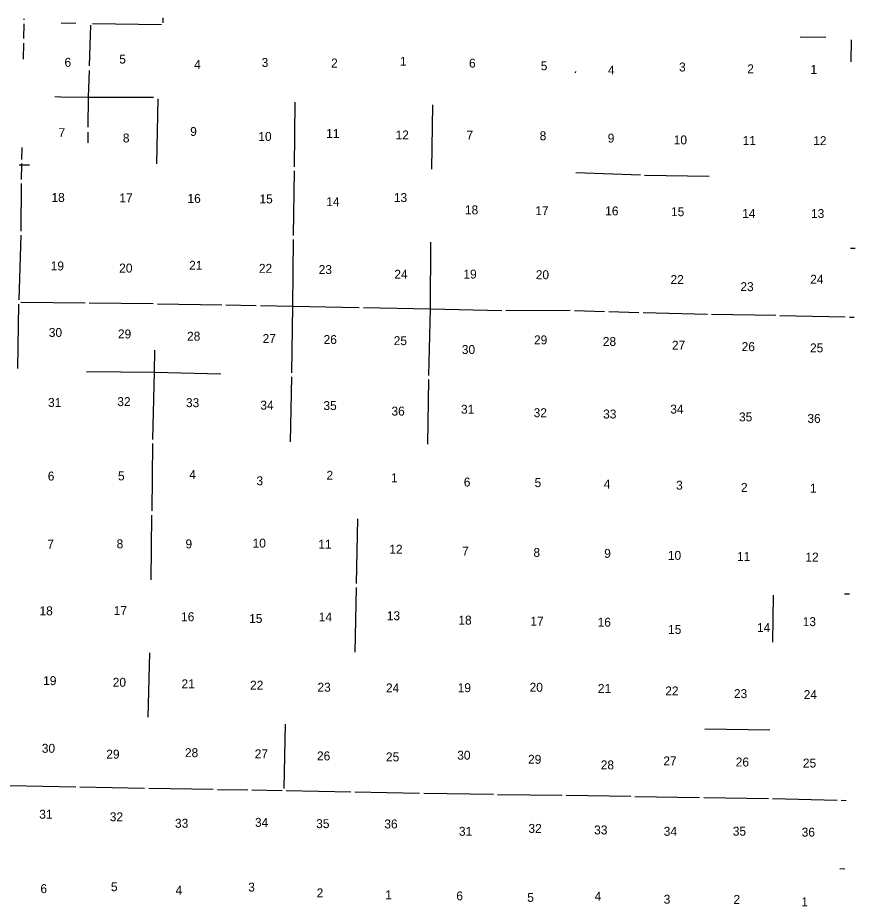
# Model space of a CAD drawing. Extents: x -2933025 to 31692252, y -2344676 to 23854604.
# Drawn here: x -2866805 to -2802466, y -2283621 to -2215327 of the extents above; entities that cross this region are included whole.
import ezdxf

# ---------------------------------------------------------------- set-up
doc = ezdxf.new("R2010")
doc.units = 0
doc.layers.add('tdCoSectLinePart', color=7, linetype='Continuous')
doc.layers.add('tdCoSectNmbr', color=7, linetype='Continuous')

msp = doc.modelspace()

# ---------------------------------------------------------------- linework, layer by layer
at = {"layer": 'tdCoSectLinePart'}
for points in [[(-2866313, -2215488), (-2866311, -2215399)], [(-2855629, -2215718), (-2855642, -2215327)], [(-2866337, -2216910), (-2866318, -2215805)], [(-2863484, -2215711), (-2862333, -2215737)], [(-2861293, -2219033), (-2861189, -2215891)], [(-2861061, -2215765), (-2855771, -2215853)], [(-2806705, -2216789), (-2804719, -2216827)], [(-2866366, -2218516), (-2866344, -2217282)], [(-2802771, -2218724), (-2802743, -2217021)], [(-2861373, -2221424), (-2861305, -2219382)], [(-2823945, -2219549), (-2823941, -2219450)], [(-2863951, -2221387), (-2863497, -2221393)], [(-2863494, -2221393), (-2861373, -2221424)], [(-2861395, -2223734), (-2861373, -2221424)], [(-2861373, -2221424), (-2856373, -2221442)], [(-2856109, -2226557), (-2856026, -2221560)], [(-2845544, -2226782), (-2845485, -2221821)], [(-2834998, -2226973), (-2834919, -2222014)], [(-2861407, -2224952), (-2861399, -2224111)], [(-2866492, -2226209), (-2866478, -2225298)], [(-2866709, -2226627), (-2866499, -2226632)], [(-2866510, -2227757), (-2866499, -2226632)], [(-2866499, -2226632), (-2866497, -2226536)], [(-2866499, -2226632), (-2865902, -2226638)], [(-2845620, -2232051), (-2845549, -2227099)], [(-2823939, -2227230), (-2818963, -2227413)], [(-2818646, -2227422), (-2813692, -2227513)], [(-2866549, -2231720), (-2866513, -2228074)], [(-2866711, -2237018), (-2866555, -2232037)], [(-2845676, -2237501), (-2845624, -2232367)], [(-2835102, -2237711), (-2835071, -2232575)], [(-2802839, -2233036), (-2802466, -2233044)], [(-2866558, -2237179), (-2861631, -2237235)], [(-2861315, -2237239), (-2856398, -2237301)], [(-2866802, -2242295), (-2866719, -2237334)], [(-2856081, -2237306), (-2851124, -2237389)], [(-2850808, -2237395), (-2848485, -2237443)], [(-2848168, -2237450), (-2845676, -2237501)], [(-2845753, -2242619), (-2845676, -2237501)], [(-2845676, -2237501), (-2840577, -2237604)], [(-2840255, -2237610), (-2835102, -2237711)], [(-2835224, -2242820), (-2835102, -2237711)], [(-2835102, -2237711), (-2829616, -2237817)], [(-2829299, -2237820), (-2824357, -2237813)], [(-2824041, -2237818), (-2821724, -2237896)], [(-2821407, -2237907), (-2819085, -2237985)], [(-2818768, -2237994), (-2813818, -2238113)], [(-2813502, -2238120), (-2808571, -2238197)], [(-2808255, -2238203), (-2803235, -2238325)], [(-2802918, -2238334), (-2802549, -2238345)], [(-2856307, -2242570), (-2856284, -2240878)], [(-2861513, -2242515), (-2856307, -2242570)], [(-2856419, -2247733), (-2856307, -2242570)], [(-2856307, -2242570), (-2851205, -2242686)], [(-2845864, -2247921), (-2845759, -2242936)], [(-2835302, -2248113), (-2835230, -2243139)], [(-2856491, -2253237), (-2856425, -2248050)], [(-2856566, -2258522), (-2856495, -2253553)], [(-2840770, -2258810), (-2840673, -2253843)], [(-2840880, -2264093), (-2840776, -2259127)], [(-2808788, -2263324), (-2808735, -2259707)], [(-2803278, -2259595), (-2802903, -2259616)], [(-2856776, -2269088), (-2856665, -2264136)], [(-2846342, -2274573), (-2846243, -2269619)], [(-2814014, -2269988), (-2809021, -2270070)], [(-2867418, -2274344), (-2862357, -2274442)], [(-2862040, -2274448), (-2857061, -2274535)], [(-2856744, -2274541), (-2851781, -2274633)], [(-2851465, -2274639), (-2849142, -2274681)], [(-2848825, -2274686), (-2846504, -2274728)], [(-2846187, -2274734), (-2841222, -2274823)], [(-2840905, -2274828), (-2835936, -2274918)], [(-2835621, -2274924), (-2830264, -2275016)], [(-2829947, -2275021), (-2824981, -2275091)], [(-2824664, -2275096), (-2819704, -2275172)], [(-2819387, -2275177), (-2814423, -2275255)], [(-2814106, -2275260), (-2809138, -2275343)], [(-2808821, -2275350), (-2803853, -2275468)], [(-2803536, -2275478), (-2803167, -2275494)], [(-2803644, -2280724), (-2803275, -2280745)]]:
    msp.add_lwpolyline(points, dxfattribs=at)

# ---------------------------------------------------------------- texts
at = {"layer": 'tdCoSectNmbr'}
for s, height, rotation, p in [('5', 686, 359.93563, (-2859007, -2218848)), ('6', 686, 359.93488, (-2863215, -2219093)), ('4', 686, 359.93644, (-2853263, -2219269)), ('3', 686, 359.93719, (-2848068, -2219103)), ('2', 686, 359.93796, (-2842735, -2219151)), ('1', 686, 359.93871, (-2837451, -2219017)), ('6', 686, 359.93949, (-2832136, -2219156)), ('5', 686, 359.94029, (-2826625, -2219372)), ('3', 686, 359.9424, (-2816000, -2219455)), ('4', 686, 359.94161, (-2821461, -2219684)), ('2', 686, 359.94316, (-2810762, -2219595)), ('1', 686, 359.94385, (-2805906, -2219641)), ('7', 686, 359.93499, (-2863675, -2224500)), ('8', 686, 359.9357, (-2858732, -2224912)), ('9', 686, 359.93644, (-2853560, -2224412)), ('10', 686.4, 359.93723, (-2848323, -2224791)), ('11', 686.4, 359.93797, (-2843114, -2224567)), ('12', 686.4, 359.93875, (-2837780, -2224680)), ('7', 686, 359.93951, (-2832332, -2224695)), ('8', 686, 359.94033, (-2826710, -2224743)), ('9', 686, 359.94162, (-2821483, -2224922)), ('10', 686.4, 359.94238, (-2816409, -2225057)), ('11', 686.4, 359.94314, (-2811114, -2225100)), ('12', 686.4, 359.94393, (-2805697, -2225117)), ('18', 686.4, 359.93497, (-2864217, -2229483)), ('17', 686.4, 359.93573, (-2859003, -2229520)), ('16', 686.4, 359.93648, (-2853767, -2229553)), ('15', 686.4, 359.93728, (-2848237, -2229596)), ('13', 686.4, 359.93877, (-2837911, -2229494)), ('14', 686.4, 359.93802, (-2843106, -2229808)), ('18', 686.4, 359.93957, (-2832452, -2230439)), ('17', 686.4, 359.94035, (-2827044, -2230499)), ('16', 686.4, 359.94163, (-2821678, -2230517)), ('15', 686.4, 359.94236, (-2816617, -2230576)), ('14', 686.4, 359.94316, (-2811151, -2230719)), ('13', 686.4, 359.94392, (-2805864, -2230721)), ('19', 686.4, 359.93502, (-2864274, -2234747)), ('20', 686.4, 359.93576, (-2859015, -2234911)), ('21', 686.4, 359.93653, (-2853641, -2234699)), ('22', 686.4, 359.9373, (-2848284, -2234932)), ('23', 686.4, 359.93799, (-2843686, -2235026)), ('24', 686.4, 359.93883, (-2837875, -2235387)), ('19', 686.4, 359.93959, (-2832567, -2235375)), ('20', 686.4, 359.9404, (-2827010, -2235420)), ('22', 686.4, 359.94238, (-2816657, -2235789)), ('24', 686.4, 359.94393, (-2805926, -2235770)), ('23', 686.4, 359.94315, (-2811288, -2236339)), ('30', 686.4, 359.93504, (-2864422, -2239858)), ('29', 686.4, 359.93581, (-2859111, -2239975)), ('28', 686.4, 359.93658, (-2853803, -2240146)), ('27', 686.4, 359.93741, (-2847996, -2240330)), ('26', 686.4, 359.93809, (-2843309, -2240404)), ('25', 686.4, 359.93887, (-2837925, -2240492)), ('29', 686.4, 359.94042, (-2827144, -2240431)), ('28', 686.4, 359.94164, (-2821858, -2240554)), ('30', 686.4, 359.93963, (-2832690, -2241171)), ('27', 686.4, 359.94241, (-2816548, -2240841)), ('26', 686.4, 359.94318, (-2811193, -2240952)), ('25', 686.4, 359.94394, (-2805940, -2241043)), ('31', 686.4, 359.93505, (-2864480, -2245239)), ('32', 686.4, 359.93585, (-2859161, -2245176)), ('33', 686.4, 359.93661, (-2853884, -2245257)), ('34', 686.4, 359.93744, (-2848167, -2245447)), ('35', 686.4, 359.93814, (-2843323, -2245479)), ('36', 686.4, 359.93889, (-2838096, -2245904)), ('31', 686.4, 359.93966, (-2832753, -2245762)), ('32', 686.4, 359.94047, (-2827170, -2246028)), ('33', 686.4, 359.94166, (-2821836, -2246129)), ('34', 686.4, 359.94241, (-2816675, -2245749)), ('35', 686.4, 359.94317, (-2811395, -2246352)), ('36', 686.4, 359.94393, (-2806141, -2246466)), ('6', 686, 359.93511, (-2864500, -2250896)), ('5', 686, 359.93589, (-2859107, -2250885)), ('4', 686, 359.93668, (-2853628, -2250776)), ('2', 686, 359.9382, (-2843090, -2250840)), ('3', 686, 359.93743, (-2848469, -2251260)), ('1', 686, 359.93891, (-2838129, -2251025)), ('6', 686, 359.93973, (-2832539, -2251358)), ('5', 686, 359.94051, (-2827100, -2251402)), ('4', 686, 359.94167, (-2821787, -2251511)), ('3', 686, 359.94247, (-2816227, -2251602)), ('2', 686, 359.94319, (-2811242, -2251769)), ('1', 686, 359.94395, (-2805947, -2251833)), ('7', 686, 359.93515, (-2864539, -2256140)), ('8', 686, 359.93592, (-2859212, -2256108)), ('9', 686, 359.93668, (-2853920, -2256112)), ('10', 686.4, 359.93745, (-2848766, -2256053)), ('11', 686.4, 359.93817, (-2843719, -2256136)), ('12', 686.4, 359.93897, (-2838262, -2256520)), ('7', 686, 359.93976, (-2832665, -2256667)), ('8', 686, 359.94054, (-2827188, -2256770)), ('9', 686, 359.94169, (-2821750, -2256843)), ('10', 686.4, 359.94241, (-2816862, -2256995)), ('11', 686.4, 359.94317, (-2811544, -2257079)), ('12', 686.4, 359.94394, (-2806296, -2257126)), ('18', 686.4, 359.93513, (-2865137, -2261259)), ('17', 686.4, 359.93596, (-2859431, -2261241)), ('16', 686.4, 359.93671, (-2854259, -2261709)), ('15', 686.4, 359.93746, (-2849030, -2261848)), ('14', 686.4, 359.93823, (-2843684, -2261731)), ('13', 686.4, 359.93898, (-2838455, -2261635)), ('18', 686.4, 359.93978, (-2832956, -2261974)), ('17', 686.4, 359.94058, (-2827423, -2262056)), ('16', 686.4, 359.94165, (-2822258, -2262130)), ('14', 686.4, 359.94325, (-2810014, -2262547)), ('13', 686.4, 359.94393, (-2806500, -2262091)), ('15', 686.4, 359.9424, (-2816845, -2262686)), ('19', 686.4, 359.93523, (-2864856, -2266624)), ('20', 686.4, 359.936, (-2859510, -2266749)), ('21', 686.4, 359.93673, (-2854225, -2266868)), ('22', 686.4, 359.93751, (-2848961, -2266974)), ('23', 686.4, 359.93827, (-2843784, -2267130)), ('24', 686.4, 359.93903, (-2838517, -2267185)), ('19', 686.4, 359.93982, (-2833007, -2267167)), ('20', 686.4, 359.94062, (-2827483, -2267134)), ('21', 686.4, 359.94166, (-2822238, -2267220)), ('22', 686.4, 359.94242, (-2817062, -2267414)), ('23', 686.4, 359.94318, (-2811785, -2267622)), ('24', 686.4, 359.94396, (-2806427, -2267696)), ('30', 686.4, 359.93524, (-2864960, -2271824)), ('29', 686.4, 359.93597, (-2860006, -2272274)), ('28', 686.4, 359.93684, (-2853962, -2272162)), ('27', 686.4, 359.93762, (-2848601, -2272248)), ('26', 686.4, 359.93831, (-2843818, -2272410)), ('25', 686.4, 359.93907, (-2838520, -2272483)), ('30', 686.4, 359.93986, (-2833044, -2272358)), ('29', 686.4, 359.94065, (-2827601, -2272671)), ('27', 686.4, 359.94241, (-2817209, -2272797)), ('28', 686.4, 359.94172, (-2822018, -2273101)), ('26', 686.4, 359.94322, (-2811647, -2272878)), ('25', 686.4, 359.94396, (-2806487, -2272960)), ('31', 686.4, 359.93527, (-2865156, -2276893)), ('32', 686.4, 359.93606, (-2859737, -2277088)), ('33', 686.4, 359.93679, (-2854726, -2277587)), ('34', 686.4, 359.93767, (-2848581, -2277519)), ('35', 686.4, 359.93835, (-2843881, -2277616)), ('36', 686.4, 359.9391, (-2838644, -2277640)), ('31', 686.4, 359.93993, (-2832915, -2278206)), ('32', 686.4, 359.9407, (-2827572, -2277982)), ('33', 686.4, 359.94168, (-2822525, -2278101)), ('34', 686.4, 359.94246, (-2817178, -2278206)), ('35', 686.4, 359.94322, (-2811872, -2278196)), ('36', 686.4, 359.94398, (-2806581, -2278270)), ('6', 686, 359.93533, (-2865067, -2282611)), ('5', 686, 359.93609, (-2859650, -2282463)), ('4', 686, 359.93684, (-2854682, -2282724)), ('3', 686, 359.93761, (-2849098, -2282496)), ('2', 686, 359.93837, (-2843843, -2282933)), ('1', 686, 359.93912, (-2838574, -2283094)), ('6', 686, 359.93992, (-2833112, -2283168)), ('5', 686, 359.9407, (-2827665, -2283283)), ('4', 686, 359.9417, (-2822490, -2283199)), ('3', 686, 359.94246, (-2817179, -2283427)), ('2', 686, 359.94324, (-2811821, -2283438)), ('1', 686, 359.94398, (-2806602, -2283620))]:
    msp.add_text(s, height=height, rotation=rotation, dxfattribs=at).set_placement(p)

doc.saveas('drawing.dxf')
